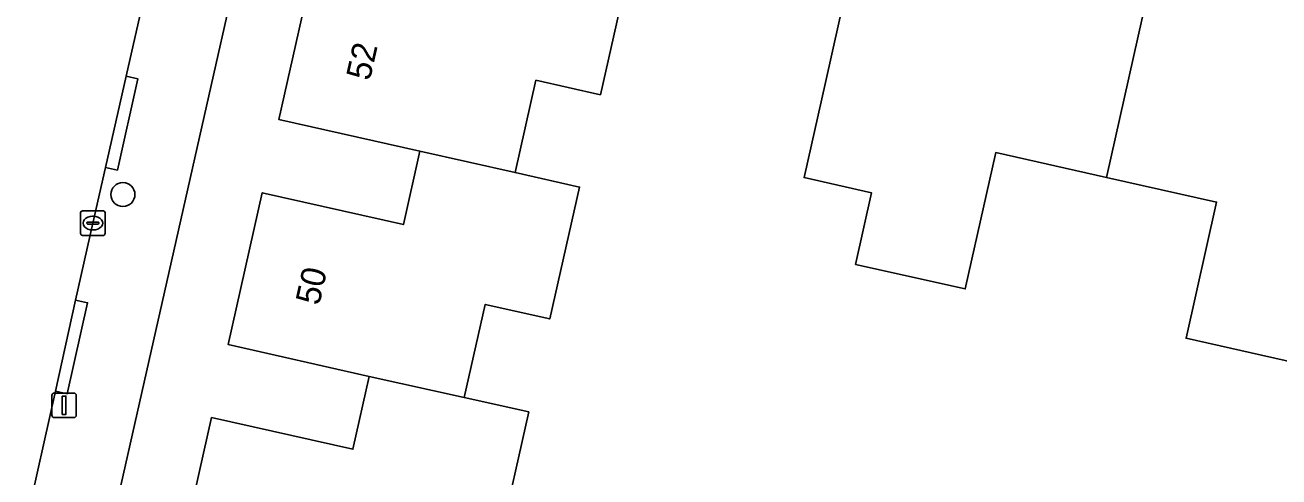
# Model space of a CAD drawing. Extents: x 161771 to 163125, y 382475 to 383179.
# Drawn here: x 162596.6 to 162647.7, y 382726.5 to 382745 of the extents above; entities that cross this region are included whole.
import ezdxf

# ---------------------------------------------------------------- set-up
doc = ezdxf.new("R2010")
doc.units = 0
for name, color, linetype in [('IMGEO_Boom', 7, 'Continuous'), ('IMGEO_Erf', 7, 'Continuous'), ('IMGEO_Kolk', 7, 'Continuous'), ('IMGEO_Lichtmast', 7, 'Continuous'), ('IMGEO_Pand', 7, 'Continuous'), ('IMGEO_Pand_nummerreeks', 7, 'Continuous'), ('IMGEO_Rijbaan_lokaal_open', 7, 'Continuous'), ('IMGEO_Voetpad_open', 7, 'Continuous')]:
    doc.layers.add(name, color=color, linetype=linetype)

msp = doc.modelspace()

# ---------------------------------------------------------------- linework, layer by layer
at = {"layer": 'IMGEO_Boom'}
msp.add_circle((162600.618, 382738.066), 0.489, dxfattribs=at)
at = {"layer": 'IMGEO_Erf'}
for points in [[(162599.628, 382713.841), (162601.392, 382713.461), (162602.247, 382713.274), (162603.637, 382719.476), (162609.393, 382718.181), (162610.056, 382721.127), (162602.841, 382722.773), (162604.234, 382728.966), (162609.991, 382727.672), (162610.658, 382730.638), (162604.905, 382731.951), (162606.297, 382738.137), (162612.054, 382736.843), (162612.727, 382739.834), (162606.97, 382741.13), (162608.36, 382747.308), (162614.117, 382746.014), (162614.784, 382748.979), (162610.242, 382750), (162609.03, 382750.287), (162610.425, 382756.488), (162616.182, 382755.194), (162616.856, 382758.145), (162610.125, 382759.664)], [(162607.756, 382758.233), (162605.899, 382750), (162598.271, 382716.192)], [(162621.291, 382747.52), (162620.079, 382742.138), (162617.452, 382742.73), (162616.603, 382738.961), (162619.23, 382738.37), (162618.018, 382732.991), (162615.391, 382733.583), (162614.534, 382729.778), (162617.163, 382729.194), (162615.952, 382723.814), (162617.135, 382723.548), (162616.293, 382719.805), (162621.713, 382718.579), (162620.505, 382713.197), (162615.362, 382714.351), (162612.738, 382714.94), (162611.862, 382711.117), (162621.667, 382708.866), (162687.264, 382694.2), (162689.87, 382693.601)], [(162668.62, 382732.531), (162664.133, 382733.537), (162659.6, 382734.553), (162658.349, 382728.974), (162653.911, 382729.968), (162654.567, 382732.894), (162651.787, 382733.517), (162649.067, 382734.127), (162648.411, 382731.201), (162643.954, 382732.2), (162645.2, 382737.759), (162640.71, 382738.765), (162636.199, 382739.776), (162634.953, 382734.217), (162630.486, 382735.218), (162631.128, 382738.141), (162628.382, 382738.757), (162629.254, 382742.64), (162630.35, 382747.518)]]:
    msp.add_lwpolyline(points, dxfattribs=at)
at = {"layer": 'IMGEO_Kolk'}
for p, q in [((162598.968, 382737.401), (162599.82, 382737.401)), ((162598.893, 382736.475), (162598.893, 382737.327)), ((162599.152, 382736.895), (162599.152, 382736.907)), ((162599.59, 382736.858), (162599.192, 382736.858)), ((162599.195, 382736.944), (162599.593, 382736.944)), ((162599.381, 382737.181), (162599.406, 382737.181)), ((162599.636, 382736.907), (162599.636, 382736.895)), ((162599.894, 382737.327), (162599.894, 382736.475)), ((162599.82, 382736.401), (162598.968, 382736.401)), ((162599.404, 382736.621), (162599.379, 382736.621))]:
    msp.add_line(p, q, dxfattribs=at)
for points in [[(162598.968, 382737.401), (162599.82, 382737.401)], [(162598.893, 382736.475), (162598.893, 382737.327)], [(162599.894, 382737.327), (162599.894, 382736.475)], [(162599.82, 382736.401), (162598.968, 382736.401)]]:
    msp.add_lwpolyline(points, dxfattribs=at)
for centre, radius, start, end in [((162598.97, 382737.325), 0.0765, 91.552, 178.448), ((162598.97, 382737.325), 0.0765, 91.552, 178.448), ((162599.818, 382737.325), 0.0765, 1.552, 88.448), ((162599.818, 382737.325), 0.0765, 1.552, 88.448), ((162599.192, 382736.904), 0.0403, 85.8775, 175.7526), ((162599.189, 382736.894), 0.0366, 178.938, 274.7102), ((162599.593, 382736.901), 0.043, 264.8664, 352.4533), ((162599.597, 382736.906), 0.0386, 1.7309, 96.639), ((162598.97, 382736.477), 0.0765, 181.552, 268.448), ((162598.97, 382736.477), 0.0765, 181.552, 268.448), ((162599.818, 382736.477), 0.0765, 271.552, 358.448), ((162599.818, 382736.477), 0.0765, 271.552, 358.448)]:
    msp.add_arc(centre, radius, start, end, dxfattribs=at)
for centre, major_axis, ratio, start_param, end_param in [((162599.38, 382736.901), (-0.387, 0.002), 0.722429, 4.712389, 7.853982), ((162599.405, 382736.901), (-0.39, 0.002), 0.717154, 1.570796, 4.712389)]:
    msp.add_ellipse(centre, major_axis=major_axis, ratio=ratio, start_param=start_param, end_param=end_param, dxfattribs=at)
at = {"layer": 'IMGEO_Lichtmast'}
for p, q in [((162597.724, 382729.064), (162597.724, 382729.864)), ((162597.724, 382729.864), (162597.724, 382729.064)), ((162597.824, 382729.964), (162598.614, 382729.964)), ((162598.614, 382729.964), (162597.824, 382729.964)), ((162598.714, 382729.864), (162598.714, 382729.064)), ((162598.714, 382729.064), (162598.714, 382729.864)), ((162598.614, 382728.964), (162597.824, 382728.964)), ((162597.824, 382728.964), (162598.614, 382728.964))]:
    msp.add_line(p, q, dxfattribs=at)
msp.add_lwpolyline([(162598.144, 382729.839), (162598.294, 382729.839), (162598.294, 382729.089), (162598.144, 382729.089), (162598.144, 382729.839)], dxfattribs=at)
for centre, start, end in [((162597.824, 382729.864), 90, 180), ((162597.824, 382729.864), 90, 180), ((162598.614, 382729.864), 0, 90), ((162598.614, 382729.864), 360, 90), ((162597.824, 382729.064), 180, 270), ((162597.824, 382729.064), 180, 270), ((162598.614, 382729.064), 270, 0), ((162598.614, 382729.064), 270, 0)]:
    msp.add_arc(centre, 0.1, start, end, dxfattribs=at)
at = {"layer": 'IMGEO_Pand'}
for points in [[(162642.534, 382746.916), (162640.042, 382747.473), (162640.606, 382750), (162640.761, 382750.693), (162634.261, 382752.144), (162633.782, 382750), (162633.091, 382746.904), (162630.35, 382747.518), (162629.254, 382742.64), (162628.382, 382738.757), (162631.128, 382738.141), (162630.486, 382735.218), (162634.953, 382734.217), (162636.199, 382739.776), (162640.71, 382738.765)], [(162651.787, 382733.517), (162653.794, 382742.271), (162651.018, 382742.891), (162652.19, 382748.141), (162645.747, 382749.645), (162644.98, 382746.37), (162642.534, 382746.916), (162640.71, 382738.765), (162645.2, 382737.759), (162643.954, 382732.2), (162648.411, 382731.201), (162649.067, 382734.127)], [(162614.784, 382748.979), (162614.117, 382746.014), (162608.36, 382747.308), (162606.97, 382741.13), (162612.727, 382739.834), (162616.603, 382738.961), (162617.452, 382742.73), (162620.079, 382742.138), (162621.291, 382747.52), (162618.679, 382748.18)], [(162610.658, 382730.638), (162614.534, 382729.778), (162615.391, 382733.583), (162618.018, 382732.991), (162619.23, 382738.37), (162616.603, 382738.961), (162612.727, 382739.834), (162612.054, 382736.843), (162606.297, 382738.137), (162604.905, 382731.951)], [(162610.658, 382730.638), (162609.991, 382727.672), (162604.234, 382728.966), (162602.841, 382722.773), (162610.056, 382721.127), (162616.293, 382719.805), (162617.135, 382723.548), (162615.952, 382723.814), (162617.163, 382729.194), (162614.534, 382729.778)]]:
    msp.add_lwpolyline(points, close=True, dxfattribs=at)
at = {"layer": 'IMGEO_Rijbaan_lokaal_open'}
msp.add_lwpolyline([(162595.803, 382720.937), (162596.659, 382724.627), (162597.863, 382730.046), (162598.691, 382733.755), (162599.394, 382736.905), (162599.906, 382739.176), (162600.746, 382742.892), (162601.958, 382748.25), (162602.345, 382750), (162602.779, 382751.967), (162603.976, 382757.328), (162603.997, 382757.896), (162607.581, 382773.892), (162607.78, 382774.384), (162609.805, 382783.398), (162613.476, 382799.893), (162614.202, 382802.934), (162607.241, 382804.436), (162606.618, 382801.867), (162604.604, 382792.908), (162604.021, 382790.493), (162600.005, 382772.85), (162596.126, 382755.943)], dxfattribs=at)
at = {"layer": 'IMGEO_Voetpad_open'}
for points in [[(162604.443, 382757.121), (162603.976, 382757.328), (162602.779, 382751.967), (162603.267, 382751.86), (162602.856, 382750), (162602.446, 382748.143), (162601.958, 382748.25), (162600.746, 382742.892), (162601.227, 382742.785), (162600.393, 382739.067), (162599.906, 382739.176), (162599.394, 382736.905), (162598.691, 382733.755), (162599.176, 382733.648), (162598.351, 382729.938), (162597.863, 382730.046), (162596.659, 382724.627), (162597.146, 382724.515), (162596.29, 382720.825), (162595.803, 382720.937), (162595.028, 382717.515)], [(162597.254, 382712.303), (162598.271, 382716.192), (162605.899, 382750)]]:
    msp.add_lwpolyline(points, dxfattribs=at)
for points in [[(162599.906, 382739.176), (162600.393, 382739.067), (162601.227, 382742.785), (162600.746, 382742.892)], [(162597.863, 382730.046), (162598.351, 382729.938), (162599.176, 382733.648), (162598.691, 382733.755)]]:
    msp.add_lwpolyline(points, close=True, dxfattribs=at)

# ---------------------------------------------------------------- texts
at = {"layer": 'IMGEO_Pand_nummerreeks'}
for s, rotation, p in [('52', 77.3205, (162610.681, 382742.681)), ('50', 77.3207, (162608.618, 382733.512))]:
    msp.add_text(s, height=1, rotation=rotation, dxfattribs=at).set_placement(p)

doc.saveas('drawing.dxf')
